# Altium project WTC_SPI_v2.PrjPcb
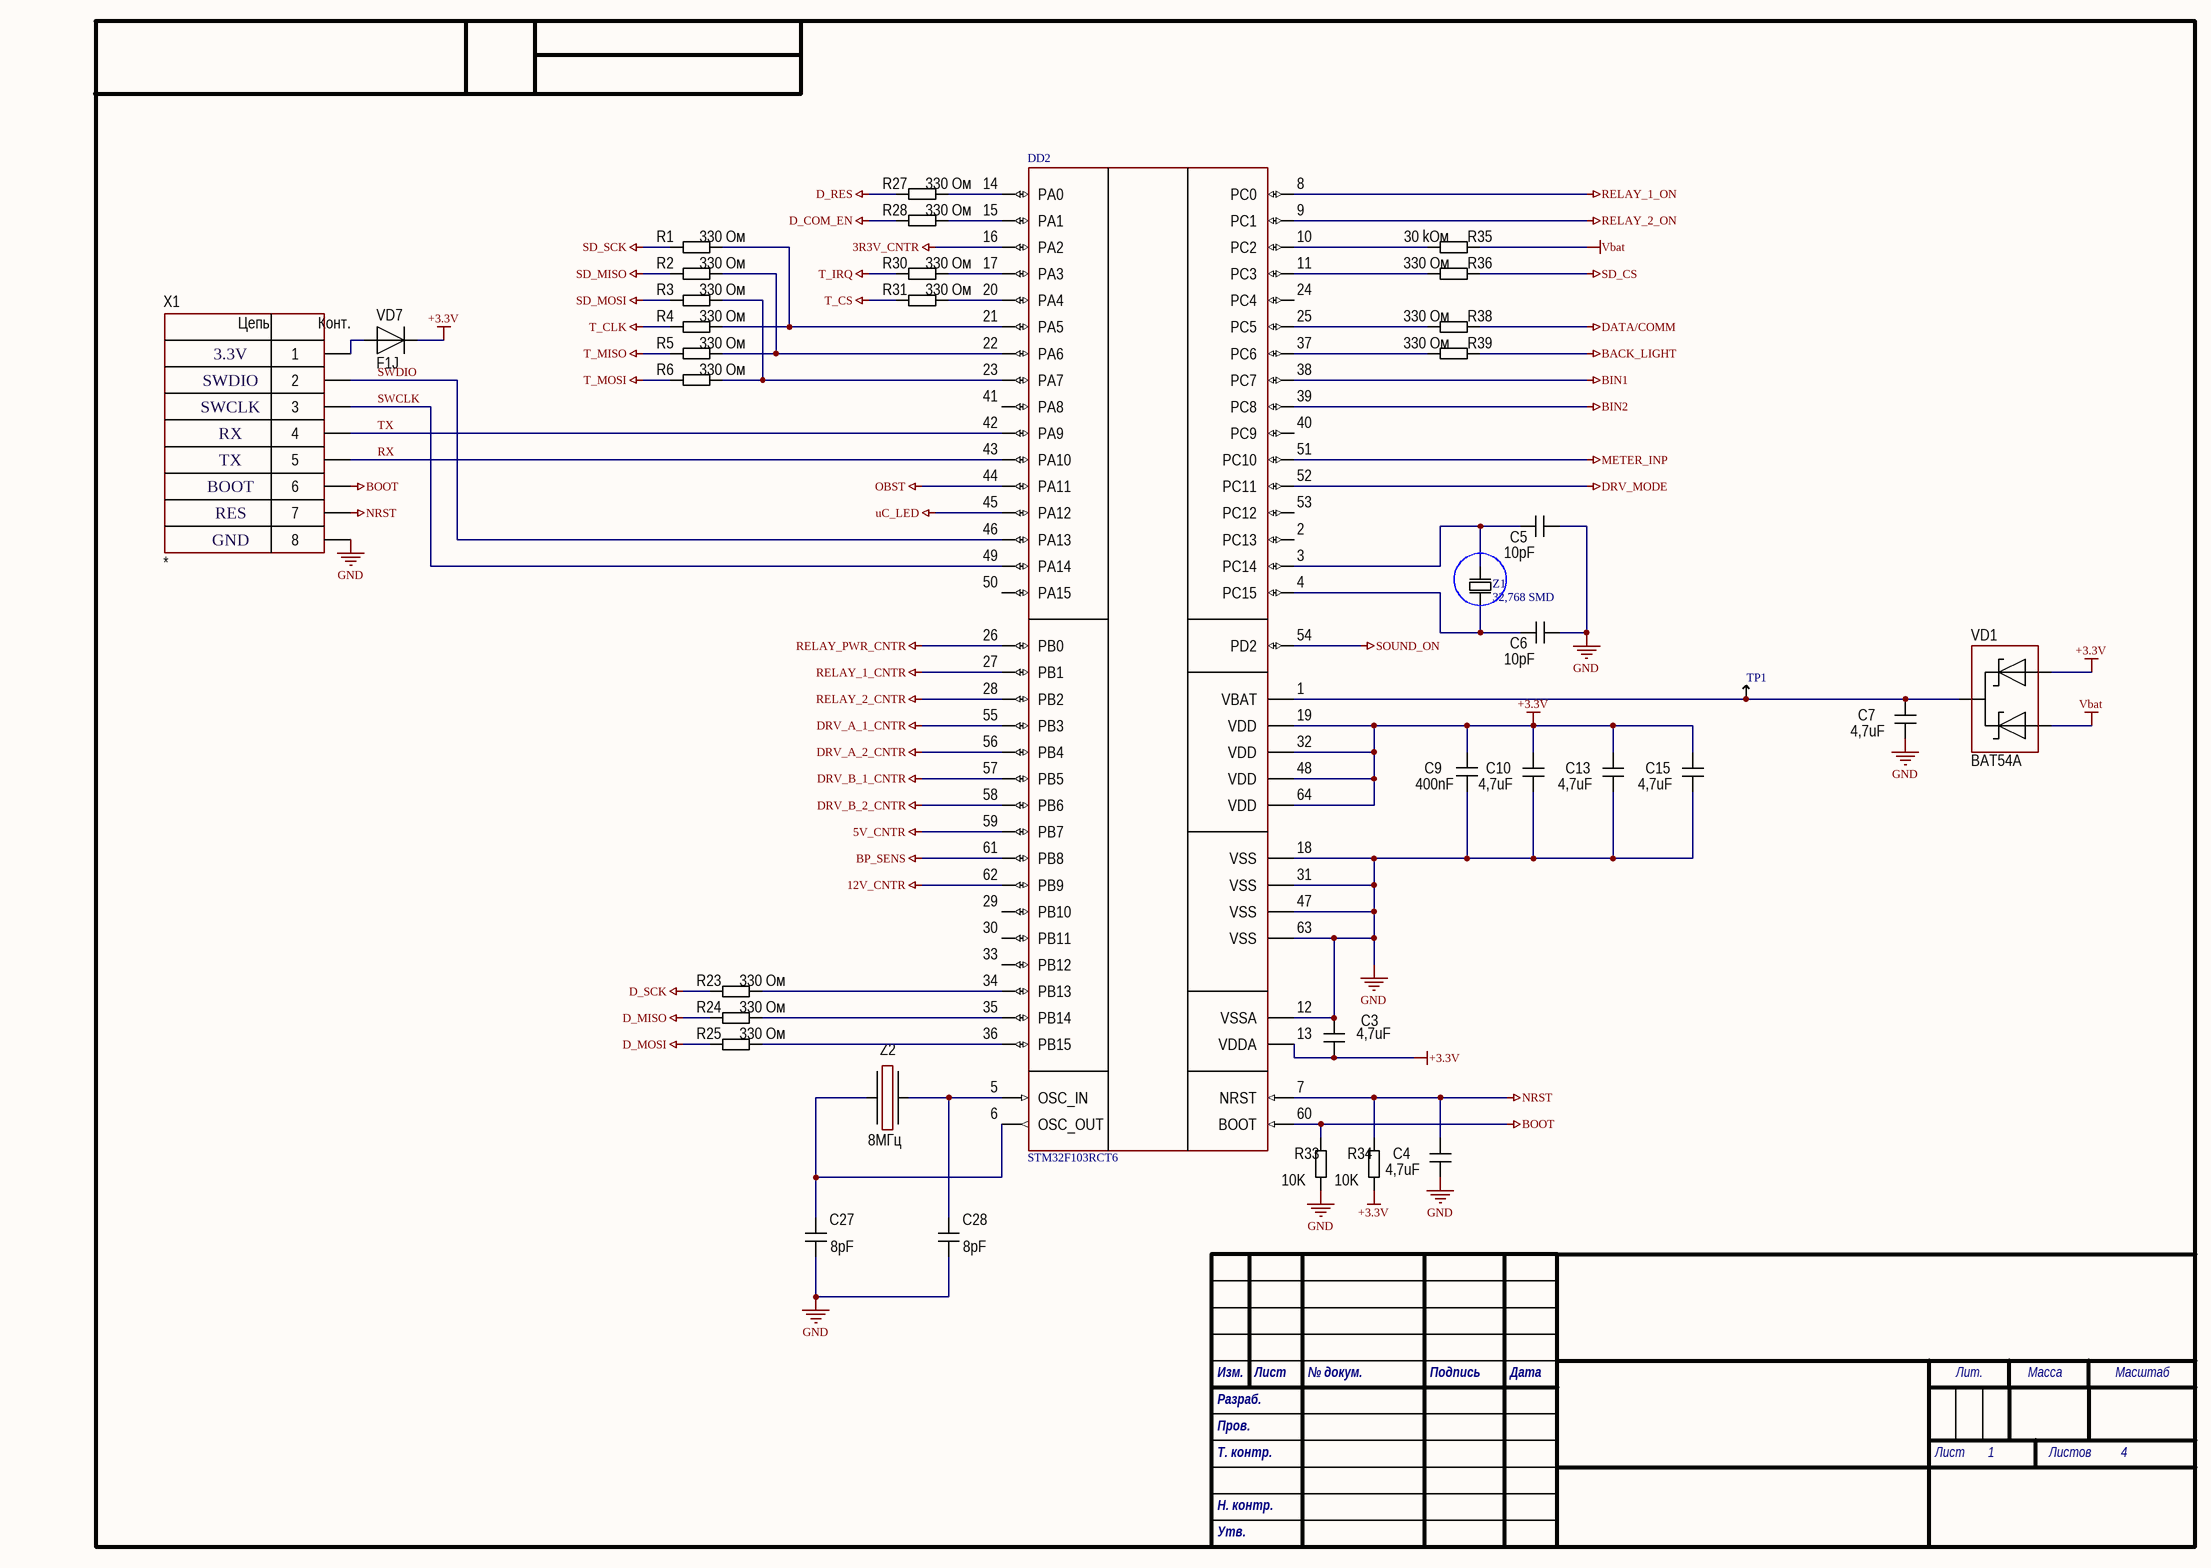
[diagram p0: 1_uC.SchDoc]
4 sheets, 165 parts. Net scope: global (net labels, ports and power ports of the same name join across sheets).
Sheets:
  1_uC.SchDoc
  2_PowerPerif.SchDoc
  3_InfoPerif.SchDoc
  4_PowerSupplie.SchDoc

## Sheet 1_uC.SchDoc
size 414 x 293 mm; SheetNumber: 1; SheetTotal: 4

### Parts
C3  4,7uF  [CH0402C]
C4  4,7uF  [CH0402C]
C5  10pF  [CH0402C]
C6  10pF  [CH0402C]
C7  4,7uF  [CH0402C]
C9  400nF  [CH0402C]
C10  4,7uF  [CH0402C]
C13  4,7uF  [CH0402C]
C15  4,7uF  [CH0402C]
C27  8pF  [CH0402C]
C28  8pF  [CH0402C]
DD2  STM32F103RCT6  [64-LQFP]
R1  330 Ом  [CH0603R]
R2  330 Ом  [CH0603R]
R3  330 Ом  [CH0603R]
R4  330 Ом  [CH0603R]
R5  330 Ом  [CH0603R]
R6  330 Ом  [CH0603R]
R23  330 Ом  [CH0603R]
R24  330 Ом  [CH0603R]
R25  330 Ом  [CH0603R]
R27  330 Ом  [CH0603R]
R28  330 Ом  [CH0603R]
R30  330 Ом  [CH0603R]
R31  330 Ом  [CH0603R]
R33  10K  [CH0805R]
R34  10K  [CH0805R]
R35  30 kОм  [CH0603R]
R36  330 Ом  [CH0603R]
R38  330 Ом  [CH0603R]
R39  330 Ом  [CH0603R]
TP1  TestPoint  (value not drawn)
VD1  BAT54A  [SOT23_123]
VD7  F1J  [SOD123F]
X1  *  [CON: PLS-8]
Z1  32,768 SMD  [SMD 32.768KHz]
Z2  8МГц  [OSC: ABM3]

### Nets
3R3V_CNTR: DD2.16(PA2)
5V_CNTR: DD2.59(PB7)
12V_CNTR: DD2.62(PB9)
+3.3V: C3.1 C9.1 C10.2 C13.2 C15.2 DD2.13(VDDA) DD2.19(VDD) DD2.32(VDD) DD2.48(VDD) DD2.64(VDD) R34.1 VD1.1 VD7.2
BACK_LIGHT: R39.1
BIN1: DD2.38(PC7)
BIN2: DD2.39(PC8)
BOOT: DD2.60(BOOT) R33.2 X1.6
BP_SENS: DD2.61(PB8)
D_COM_EN: R28.1
D_MISO: R24.1
D_MOSI: R25.1
D_RES: R27.1
D_SCK: R23.1
DATA/COMM: R38.1
DRV_A_1_CNTR: DD2.55(PB3)
DRV_A_2_CNTR: DD2.56(PB4)
DRV_B_1_CNTR: DD2.57(PB5)
DRV_B_2_CNTR: DD2.58(PB6)
DRV_MODE: DD2.52(PC11)
GND: C3.2 C4.1 C5.2 C6.1 C7.1 C9.2 C10.1 C13.1 C15.1 C27.1 C28.1 DD2.12(VSSA) DD2.18(VSS) DD2.31(VSS) DD2.47(VSS) DD2.63(VSS) R33.1 X1.8
METER_INP: DD2.51(PC10)
NRST: C4.2 DD2.7(NRST) R34.2 X1.7
OBST: DD2.44(PA11)
RELAY_1_CNTR: DD2.27(PB1)
RELAY_1_ON: DD2.8(PC0)
RELAY_2_CNTR: DD2.28(PB2)
RELAY_2_ON: DD2.9(PC1)
RELAY_PWR_CNTR: DD2.26(PB0)
RX: DD2.43(PA10) X1.5
SD_CS: R36.1
SD_MISO: R2.1
SD_MOSI: R3.1
SD_SCK: R1.1
SOUND_ON: DD2.54(PD2)
T_CLK: R4.1
T_CS: R31.1
T_IRQ: R30.1
T_MISO: R5.1
T_MOSI: R6.1
TX: DD2.42(PA9) X1.4
uC_LED: DD2.45(PA12)
Vbat: R35.1 VD1.3
SWCLK: DD2.49(PA14) X1.3
SWDIO: DD2.46(PA13) X1.2
NetC5_1: C5.1 DD2.3(PC14) Z1.1
NetC6_2: C6.2 DD2.4(PC15) Z1.2
NetC7_2: C7.2 DD2.1(VBAT) TP1.0 VD1.2
NetC27_2: C27.2 DD2.6(OSC_OUT) Z2.1
NetC28_2: C28.2 DD2.5(OSC_IN) Z2.3
NetDD2_10: DD2.10(PC2) R35.2
NetDD2_11: DD2.11(PC3) R36.2
NetDD2_14: DD2.14(PA0) R27.2
NetDD2_15: DD2.15(PA1) R28.2
NetDD2_17: DD2.17(PA3) R30.2
NetDD2_20: DD2.20(PA4) R31.2
NetDD2_21: DD2.21(PA5) R1.2 R4.2
NetDD2_22: DD2.22(PA6) R2.2 R5.2
NetDD2_23: DD2.23(PA7) R3.2 R6.2
NetDD2_25: DD2.25(PC5) R38.2
NetDD2_34: DD2.34(PB13) R23.2
NetDD2_35: DD2.35(PB14) R24.2
NetDD2_36: DD2.36(PB15) R25.2
NetDD2_37: DD2.37(PC6) R39.2
NetVD7_1: VD7.1 X1.1

Not connected (* = marked no-connect by the designer): DD2 2(PC13) 24(PC4) 29(PB10) 30(PB11) 33(PB12) 40(PC9) 41(PA8) 50(PA15) 53(PC12)

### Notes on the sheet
- 3.3V
- SWDIO
- SWCLK
- RX
- TX
- BOOT
- RES
- GND

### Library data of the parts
C3-C6 C9 C10 C13 C15 C27 C28 = Capacitor: 0402
C7 = Capacitor
DD2 = STM32F103RCT6: Cortex-M3 (64-LQFP)
R1-R6 R23-R25 R27 R28 R30 R31 R35 R36 R38 R39 = Resistor: 0603
R33 R34 = Resistor: 0805
VD1 = Diod Schottky Array v.1: SOT-23
VD7 = Diod
X1 = 8-Connector: Pin header 8
Z1 = Kvarc_32,768: 32,768 kHz SMD 8mm x 3.8mm 12,5pF
Z2 = Oscillator: NX5032GA-8MHz

## Sheet 2_PowerPerif.SchDoc
size 414 x 293 mm; SheetNumber: 2; SheetTotal: 4
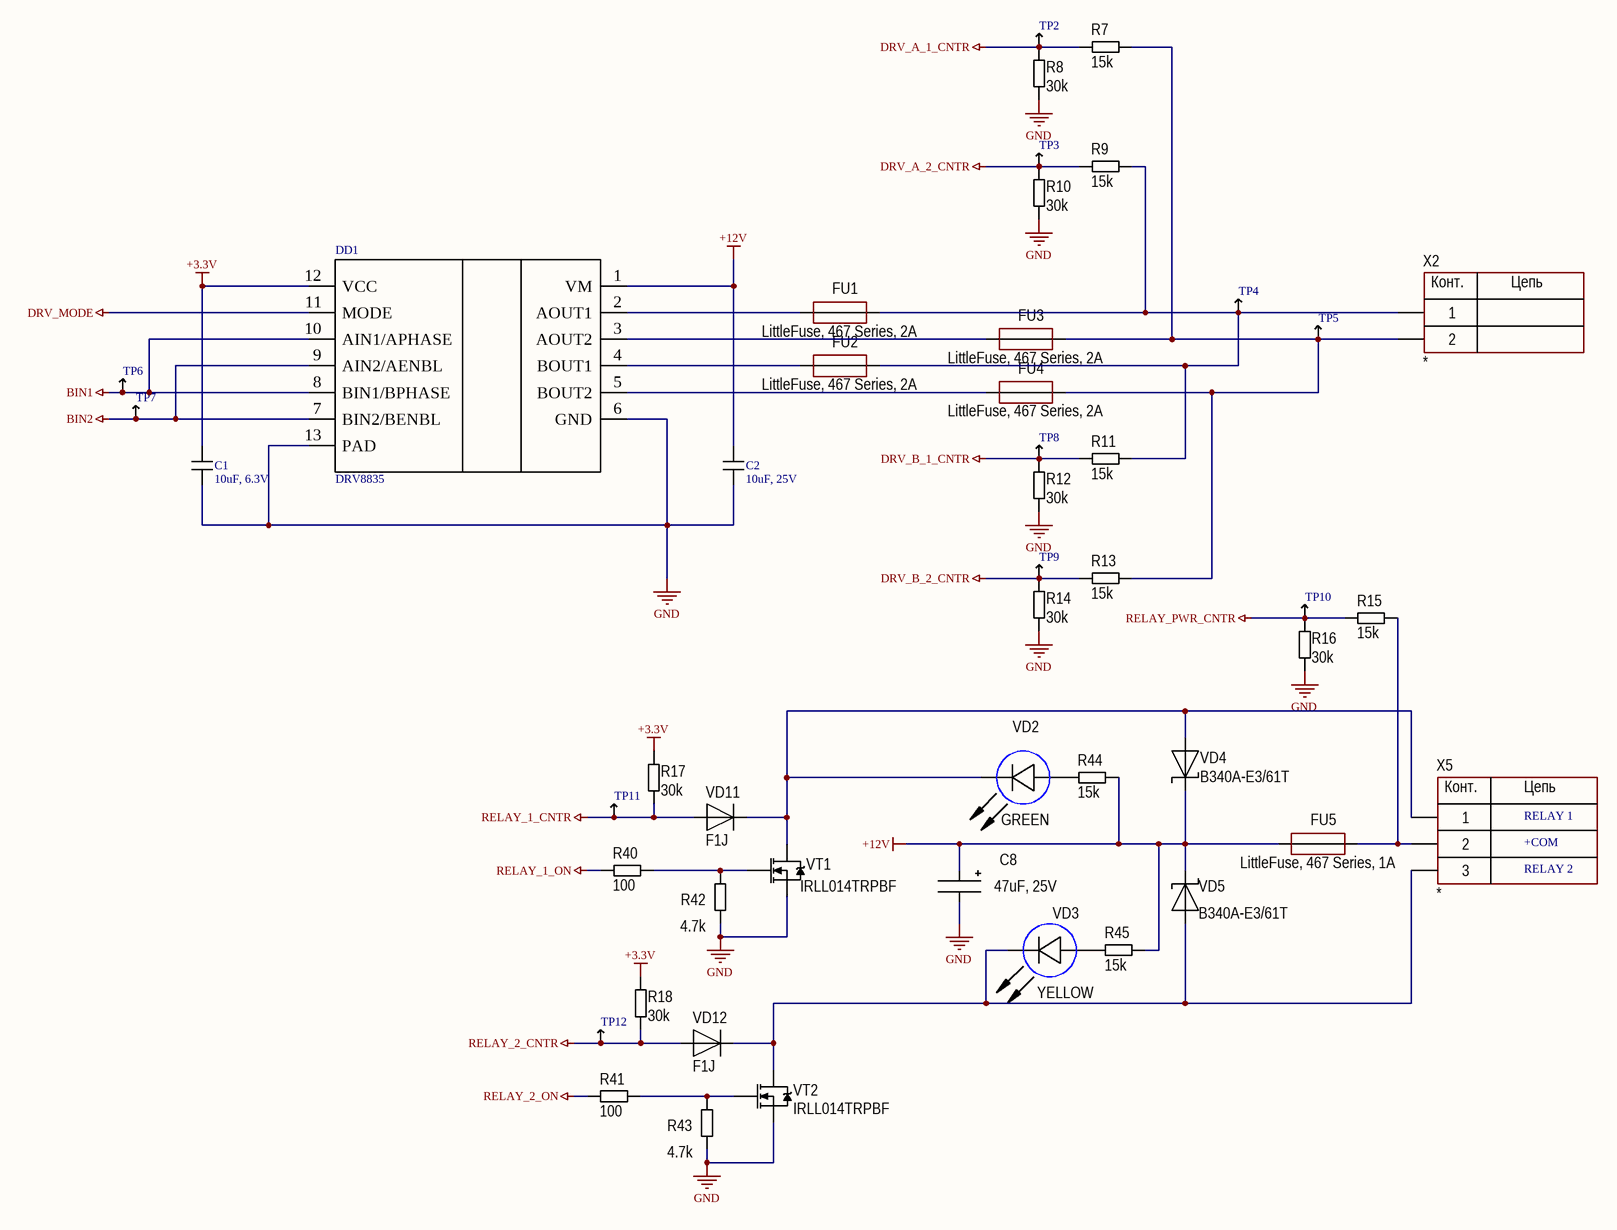
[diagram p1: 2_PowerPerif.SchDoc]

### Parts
C1  10uF, 6.3V  [C_0603]
C2  10uF, 25V  [C_0603]
C8  47uF, 25V  [D8C3.2H12]
DD1  DRV8835  [WSON12]
FU1  LittleFuse, 467 Series, 2A  [CH0603F]
FU2  LittleFuse, 467 Series, 2A  [CH0603F]
FU3  LittleFuse, 467 Series, 2A  [CH0603F]
FU4  LittleFuse, 467 Series, 2A  [CH0603F]
FU5  LittleFuse, 467 Series, 1A  [CH0603F]
R7  15k  [CH0805R]
R8  30k  [CH0805R]
R9  15k  [CH0805R]
R10  30k  [CH0805R]
R11  15k  [CH0805R]
R12  30k  [CH0805R]
R13  15k  [CH0805R]
R14  30k  [CH0805R]
R15  15k  [CH0805R]
R16  30k  [CH0805R]
R17  30k  [CH0805R]
R18  30k  [CH0805R]
R40  100  [CH0805R]
R41  100  [CH0805R]
R42  4.7k  [CH0805R]
R43  4.7k  [CH0805R]
R44  15k  [CH0805R]
R45  15k  [CH0805R]
TP2  TestPoint  (value not drawn)
TP3  TestPoint  (value not drawn)
TP4  TestPoint  (value not drawn)
TP5  TestPoint  (value not drawn)
TP6  TestPoint  (value not drawn)
TP7  TestPoint  (value not drawn)
TP8  TestPoint  (value not drawn)
TP9  TestPoint  (value not drawn)
TP10  TestPoint  (value not drawn)
TP11  TestPoint  (value not drawn)
TP12  TestPoint  (value not drawn)
VD2  GREEN  [CH0603LB]
VD3  YELLOW  [CH0603LB]
VD4  B340A-E3/61T  [SMA]
VD5  B340A-E3/61T  [SMA]
VD11  F1J  [SOD123F]
VD12  F1J  [SOD123F]
VT1  IRLL014TRPBF  [SOT223]
VT2  IRLL014TRPBF  [SOT223]
X2  *  [CON: CWF-2]
X5  *  [CON: 300-03P-5.0]

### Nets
+3.3V: C1.2 DD1.12(VCC) R17.2 R18.2
+12V: C2.2 C8.1 DD1.1(VM) FU5.1 R44.2 R45.2 VD4.2 VD5.2
BIN1: DD1.8(BIN1/BPHASE) DD1.10(AIN1/APHASE) TP6.0
BIN2: DD1.7(BIN2/BENBL) DD1.9(AIN2/AENBL) TP7.0
DRV_A_1_CNTR: R7.1 R8.2 TP2.0
DRV_A_2_CNTR: R9.1 R10.2 TP3.0
DRV_B_1_CNTR: R11.1 R12.2 TP8.0
DRV_B_2_CNTR: R13.1 R14.2 TP9.0
DRV_MODE: DD1.11(MODE)
GND: C1.1 C2.1 C8.2 DD1.6(GND) DD1.13(PAD) R8.1 R10.1 R12.1 R14.1 R16.1 R42.1 R43.1 VT1.3(S) VT2.3(S)
RELAY_1_CNTR: R17.1 TP11.0 VD11.1
RELAY_1_ON: R40.2
RELAY_2_CNTR: R18.1 TP12.0 VD12.1
RELAY_2_ON: R41.2
RELAY_PWR_CNTR: R15.1 R16.2 TP10.0
NetDD1_2: DD1.2(AOUT1) FU1.1
NetDD1_3: DD1.3(AOUT2) FU3.1
NetDD1_4: DD1.4(BOUT1) FU2.1
NetDD1_5: DD1.5(BOUT2) FU4.1
NetFU1_2: FU1.2 FU2.2 R9.2 R11.2 TP4.0 X2.1
NetFU3_2: FU3.2 FU4.2 R7.2 R13.2 TP5.0 X2.2
NetFU5_2: FU5.2 R15.2 X5.2
NetR40_1: R40.1 R42.2 VT1.1(G)
NetR41_1: R41.1 R43.2 VT2.1(G)
NetR44_1: R44.1 VD2.1(A)
NetR45_1: R45.1 VD3.1(A)
NetVD2_2: VD2.2(C) VD4.1 VD11.2 VT1.2(D) X5.1
NetVD3_2: VD3.2(C) VD5.1 VD12.2 VT2.2(D) X5.3

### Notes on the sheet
- RELAY 1
- +COM
- RELAY 2

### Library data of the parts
C1 C2 = C_SMD
C8 = AlumCap
DD1 = DRV8835: Driver
FU1-FU5 = Fuse
R7-R18 R40-R45 = Resistor
VD2 VD3 = LED_1
VD4 VD5 = Diod Schottky
VD11 VD12 = Diod
VT1 VT2 = N-chanel: Mosfet
X2 = 2-Connector
X5 = 3-Connector

## Sheet 3_InfoPerif.SchDoc
size 414 x 293 mm; SheetNumber: 3; SheetTotal: 4
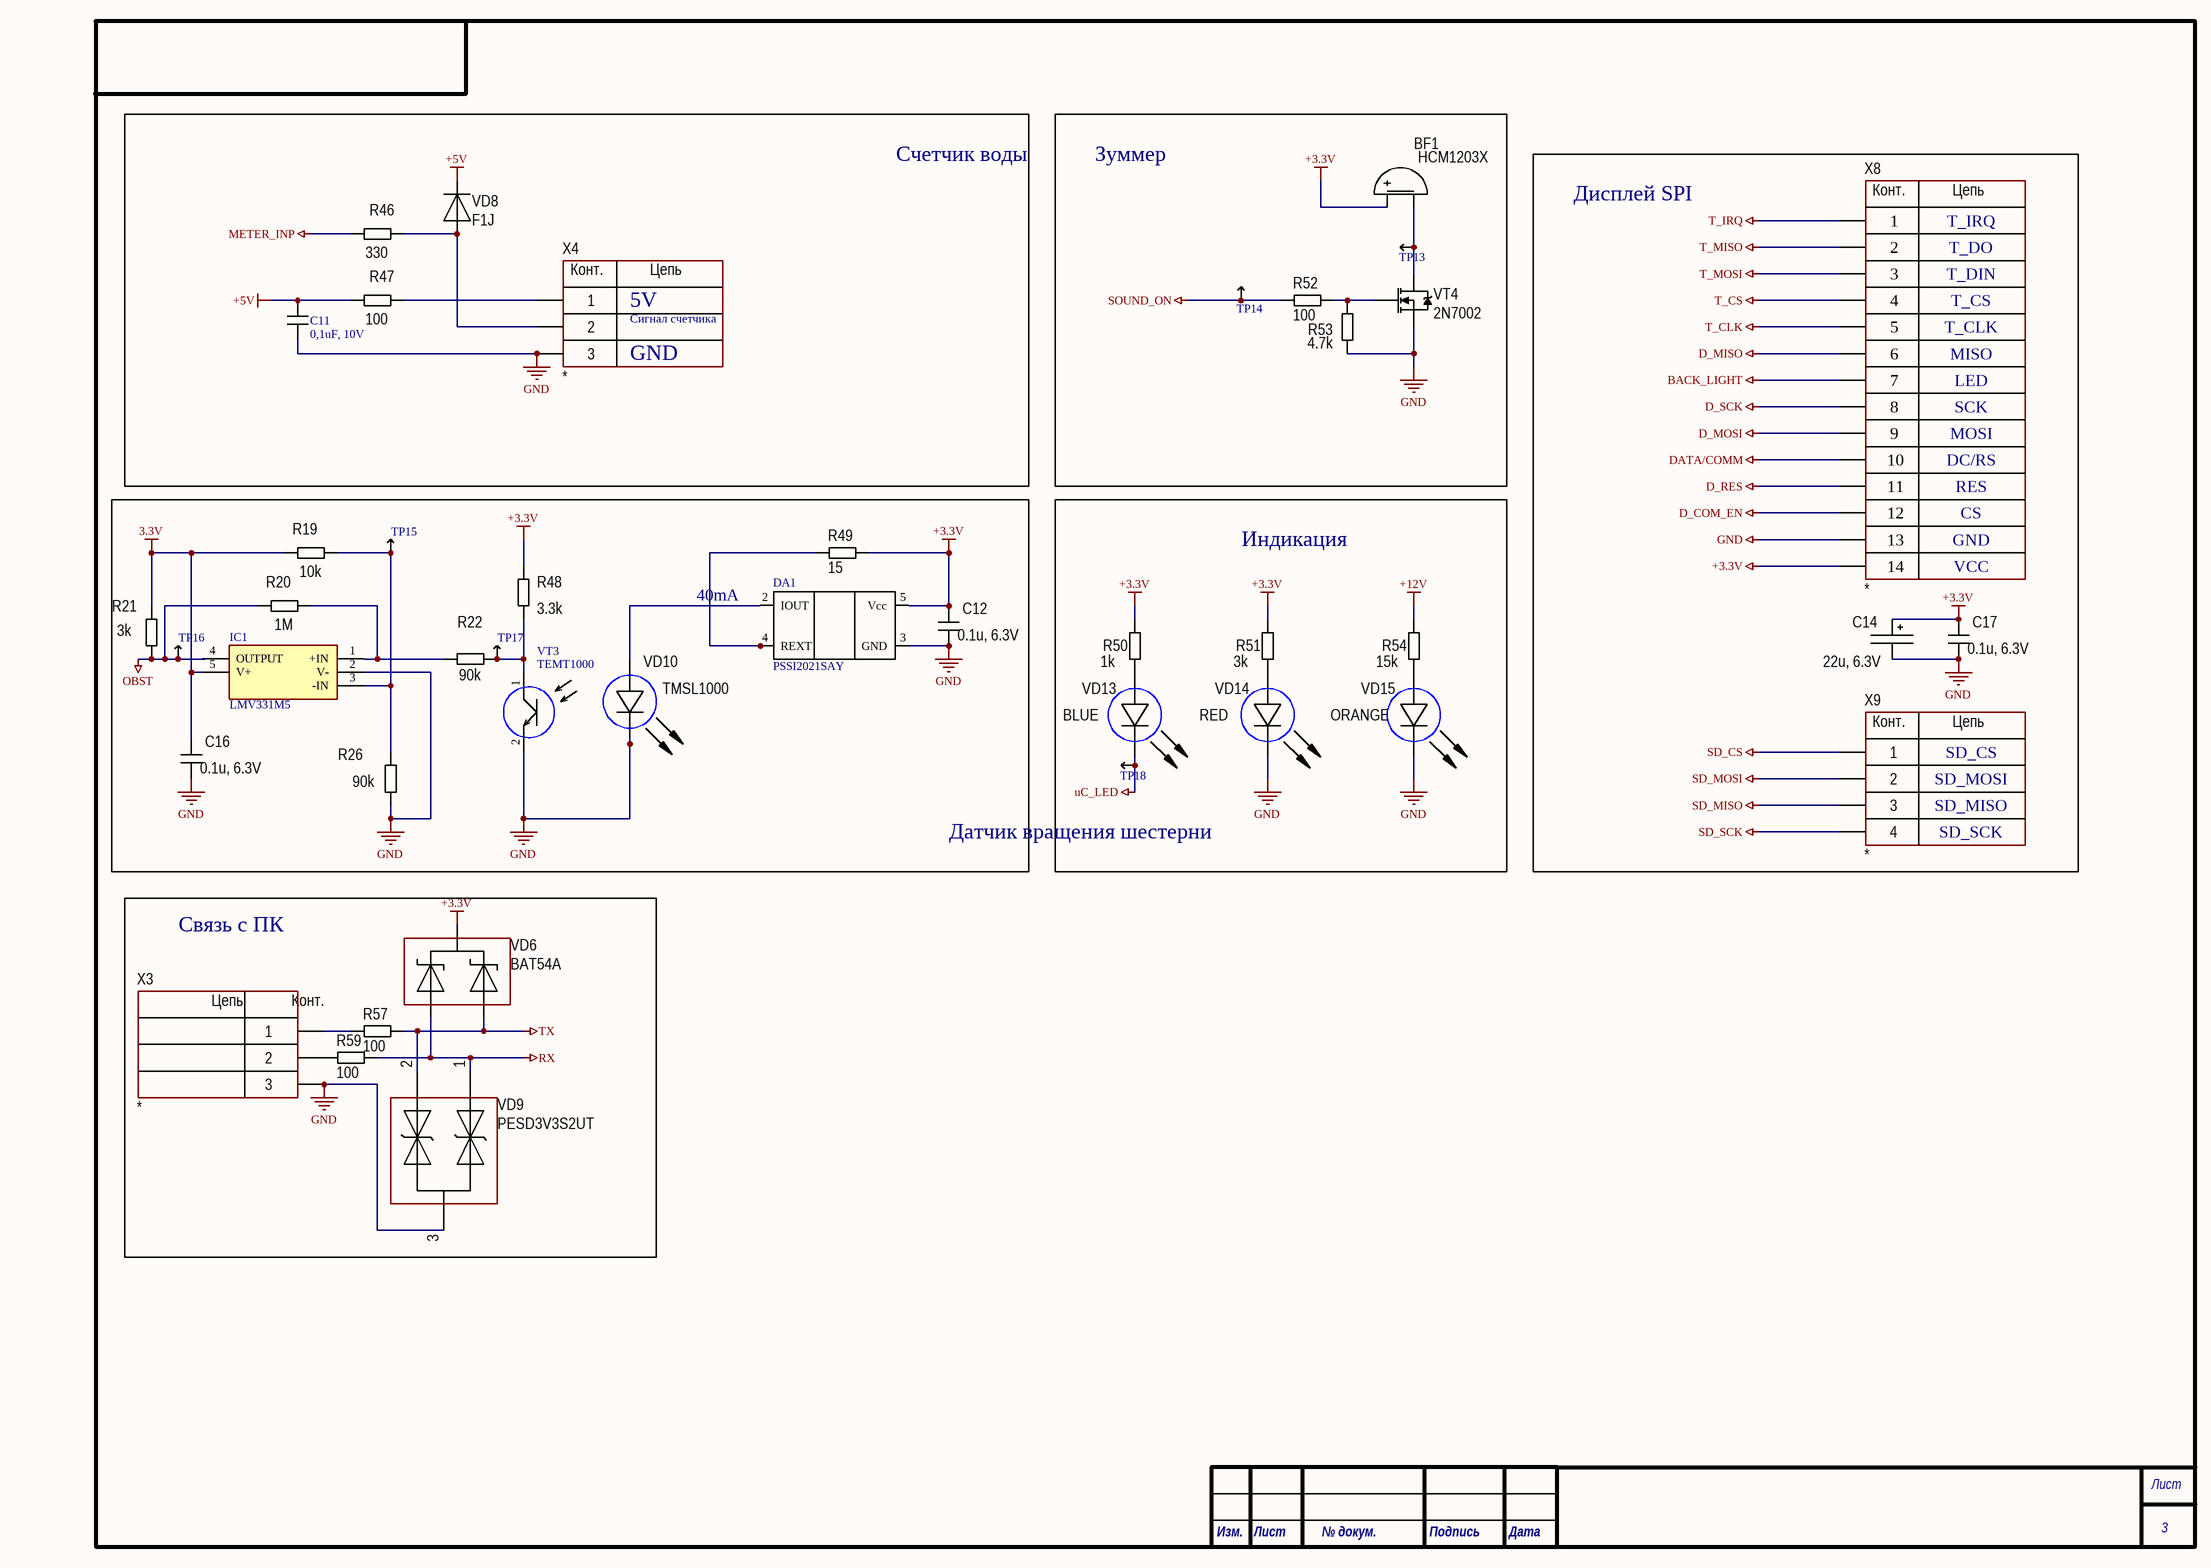
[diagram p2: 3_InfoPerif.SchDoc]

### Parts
BF1  HCM1203X  [BUZ: AI-1223-TWT-3V-2-R]
C11  0,1uF, 10V  [C_0603]
C12  0.1u, 6.3V  [CH0805C]
C14  22u, 6.3V  [TANTAL_B]
C16  0.1u, 6.3V  [CH0805C]
C17  0.1u, 6.3V  [CH0805C]
DA1  PSSI2021SAY  [SOT353]
IC1  LMV331M5  [SOT95P280X145-5N]
R19  10k  [CH0805R]
R20  1M  [CH0805R]
R21  3k  [CH0805R]
R22  90k  [CH0805R]
R26  90k  [CH0805R]
R46  330  [CH0805R]
R47  100  [CH2512R]
R48  3.3k  [CH0805R]
R49  15  [CH0805R]
R50  1k  [CH0805R]
R51  3k  [CH0805R]
R52  100  [CH0805R]
R53  4.7k  [CH0805R]
R54  15k  [CH0805R]
R57  100  [CH0805R]
R59  100  [CH0805R]
TP13  TestPoint  (value not drawn)
TP14  TestPoint  (value not drawn)
TP15  TestPoint  (value not drawn)
TP16  TestPoint  (value not drawn)
TP17  TestPoint  (value not drawn)
TP18  TestPoint  (value not drawn)
VD6  BAT54A  [SOT23_123]
VD8  F1J  [SOD123F]
VD9  PESD3V3S2UT  [SOT23_132]
VD10  TMSL1000  [TSML1000]
VD13  BLUE  [CH0603LB]
VD14  RED  [CH0603LB]
VD15  ORANGE  [CH0603LB]
VT3  TEMT1000  [TEMT1000]
VT4  2N7002  [SOT23_123]
X3  *  [CON: CWF-3]
X4  *  [CON: CWF-3]
X8  *  [DS1024-14]
X9  *  [DS1023-4]

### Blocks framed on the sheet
Зуммер: BF1 R52 R53 TP13 TP14 VT4
Дисплей SPI: C14 C17 X8 X9
Датчик вращения шестерни: C12 C16 DA1 IC1 R19-R22 R26 R48 R49 TP15-TP17 VD10 VT3
Индикация: R50 R51 R54 TP18 VD13-VD15
Связь с ПК: R57 R59 VD6 VD9 X3

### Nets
3.3V: C16.2 IC1.5(V+) R19.2 R21.2
+3.3V: BF1.1(+) C12.2 C14.1 C17.2 R48.2 R49.2 R50.2 R51.2 VD6.2 X8.14
+5V: C11.2 R47.1 VD8.2
+12V: R54.2
BACK_LIGHT: X8.7
D_COM_EN: X8.12
D_MISO: X8.6
D_MOSI: X8.9
D_RES: X8.11
D_SCK: X8.8
DATA/COMM: X8.10
GND: C11.1 C12.1 C14.2 C16.1 C17.1 DA1.3(GND) IC1.2(V-) R26.1 R53.1 VD9.3 VD10.2(C) VD14.2(C) VD15.2(C) VT3.2 VT4.3(S) X3.3 X4.3 X8.13
METER_INP: R46.1
OBST: IC1.4(OUTPUT) R20.2 R21.1 TP16.0
RX: R59.2 VD6.3 VD9.1
SD_CS: X9.1
SD_MISO: X9.3
SD_MOSI: X9.2
SD_SCK: X9.4
SOUND_ON: R52.2 TP14.0
T_CLK: X8.5
T_CS: X8.4
T_IRQ: X8.1
T_MISO: X8.2
T_MOSI: X8.3
TX: R57.2 VD6.1 VD9.2
uC_LED: TP18.0 VD13.2(C)
NetBF1_2: BF1.2(-) TP13.0 VT4.2(D)
NetDA1_2: DA1.2(IOUT) VD10.1(A)
NetDA1_4: DA1.4(REXT) R49.1
NetIC1_1: IC1.1(+IN) R20.1 R22.2
NetIC1_3: IC1.3(-IN) R19.1 R26.2 TP15.0
NetR22_1: R22.1 R48.1 TP17.0 VT3.1
NetR46_2: R46.2 VD8.1 X4.2
NetR47_2: R47.2 X4.1
NetR50_1: R50.1 VD13.1(A)
NetR51_1: R51.1 VD14.1(A)
NetR52_1: R52.1 R53.2 VT4.1(G)
NetR54_1: R54.1 VD15.1(A)
NetR57_1: R57.1 X3.1
NetR59_1: R59.1 X3.2

Not connected (* = marked no-connect by the designer): DA1 5(Vcc)

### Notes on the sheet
- Счетчик воды
- T_IRQ
- 5V
- T_DO
- T_DIN
- T_CS
- GND
- Сигнал счетчика
- T_CLK
- MISO
- LED
- SCK
- MOSI
- DC/RS
- RES
- CS
- VCC
- 40mA
- SD_CS
- SD_MOSI
- SD_MISO
- SD_SCK

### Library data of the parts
BF1 = Buzzer: Manufacturer: PUI Audio, Inc.; Model: AI-1223-TWT-3V-2-R
C11 = C_SMD
C12 C16 = Capacitor: 0805
C14 = TantalCap
C17 = Capacitor
DA1 = PSSI2021SAY: Iout = 0.617/Rext + 15 µA
IC1 = LMV331M5: Integrated Circuit; Manufacturer_Name: Texas Instruments
R19-R22 R26 R46 R47 R50-R54 R57 R59 = Resistor
R48 R49 = Resistor: 0805
VD6 = Diod Schottky Array v.1
VD8 = Diod
VD9 = TVS Array
VD10 VD13-VD15 = LED_1
VT4 = N-chanel: Mosfet
X3 X4 = 3-Connector
X8 = 14-Connector
X9 = 4-Connector

## Sheet 4_PowerSupplie.SchDoc
size 414 x 293 mm; SheetNumber: 4; SheetTotal: 4; PageSetup: Record=PageOptionsZCenterHorizontal=TrueZCenterVertical=TrueZPrintScale=1.00ZXCorrection=0.00ZYCorrection=0.00ZPrintKind=1ZBorderSize=5000000ZLeftOffset=0ZBottomOffset=0ZOrientation=2ZPaperLength=1000ZPaperWidth=1000ZScale=100ZPaperSource=7ZPrintQuality=-4ZMediaType=1ZDitherType=10ZPaperKind=A3ZPrintScaleMode=0; Razrabotal: {Разработал}; Proveril: {Проверил}; Tkontr: {Т.контр.}; Nkontr: {Н.контр.}; Ytverdil: {Утвердил}; Nazvanie1: {Название1}; Nazvanie2: {Название2}; Oboznachenie: {Обозначение}
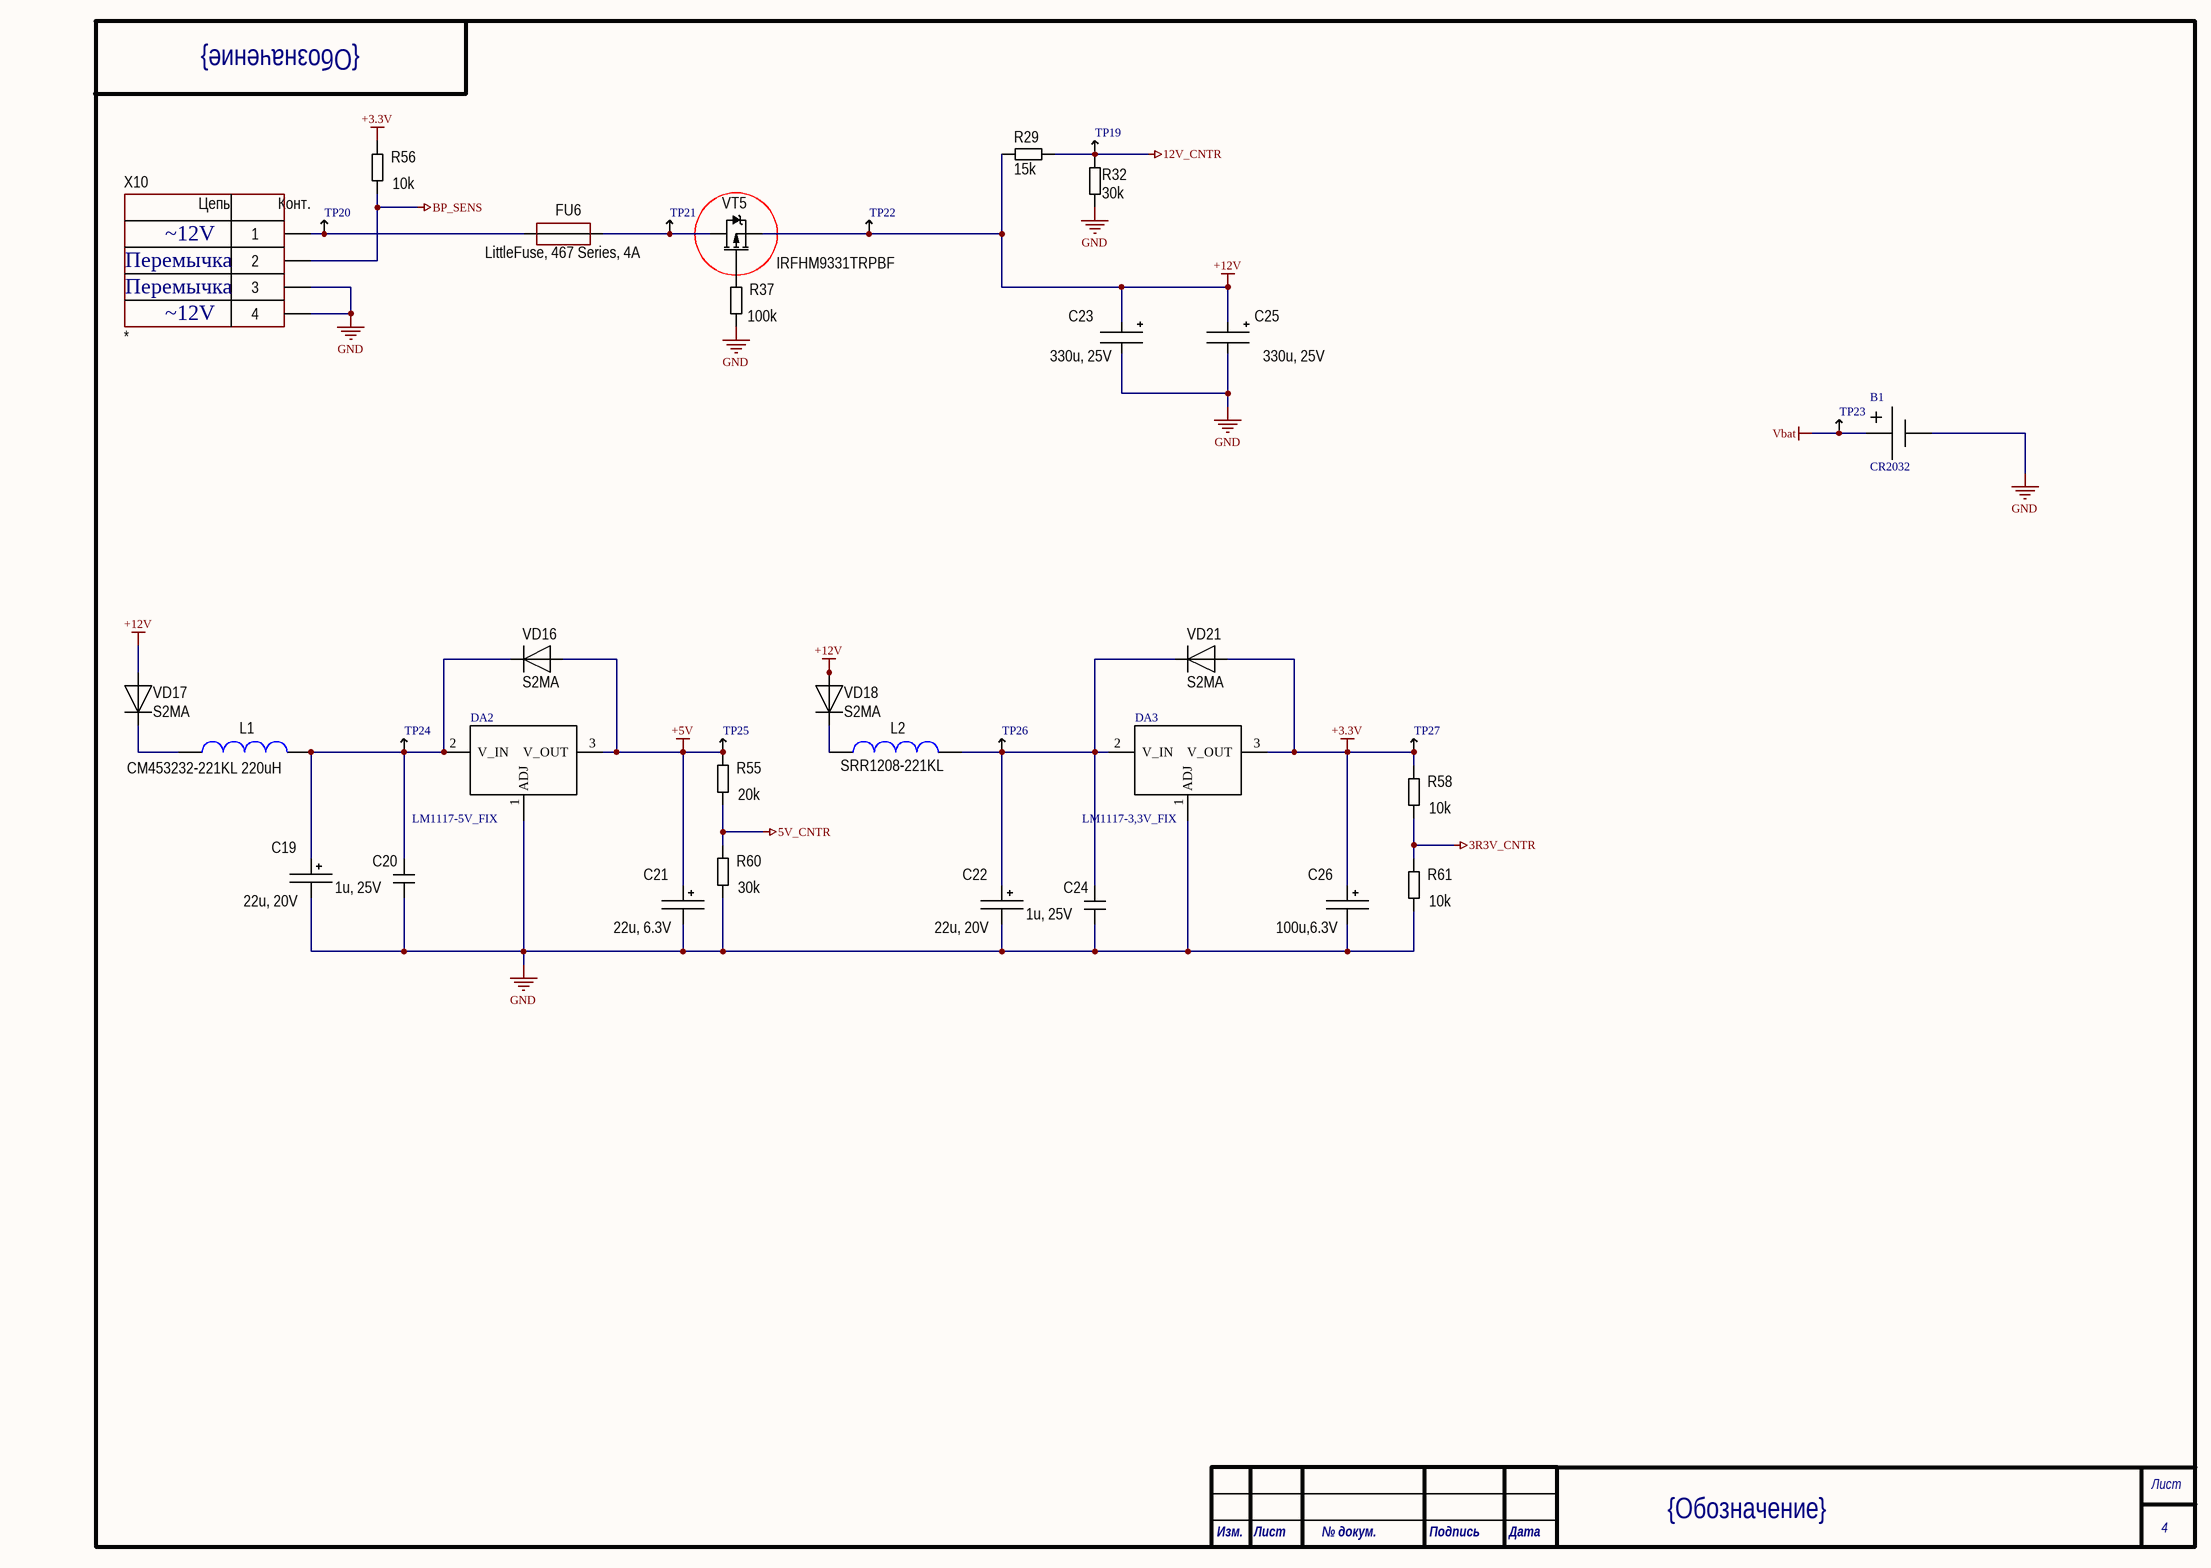
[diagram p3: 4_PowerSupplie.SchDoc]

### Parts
B1  CR2032  [CR2032]
C19  22u, 20V  [TANTAL_B]
C20  1u, 25V  [CH0805C]
C21  22u, 6.3V  [TANTAL_B]
C22  22u, 20V  [TANTAL_B]
C23  330u, 25V  [D10C4.4H10]
C24  1u, 25V  [CH0805C]
C25  330u, 25V  [D10C4.4H10]
C26  100u,6.3V  [TANTAL_B]
DA2  LM1117-5V_FIX  [SOT223_123]
DA3  LM1117-3,3V_FIX  [SOT223_123]
FU6  LittleFuse, 467 Series, 4A  [CH0603F]
L1  CM453232-221KL 220uH  [IND:1812]
L2  SRR1208-221KL  [IND: SRR1208]
R29  15k  [CH0805R]
R32  30k  [CH0805R]
R37  100k  [CH0805R]
R55  20k  [CH0805R]
R56  10k  [CH0805R]
R58  10k  [CH0805R]
R60  30k  [CH0805R]
R61  10k  [CH0805R]
TP19  TestPoint  (value not drawn)
TP20  TestPoint  (value not drawn)
TP21  TestPoint  (value not drawn)
TP22  TestPoint  (value not drawn)
TP23  TestPoint  (value not drawn)
TP24  TestPoint  (value not drawn)
TP25  TestPoint  (value not drawn)
TP26  TestPoint  (value not drawn)
TP27  TestPoint  (value not drawn)
VD16  S2MA  [SMA]
VD17  S2MA  [SMA]
VD18  S2MA  [SMA]
VD21  S2MA  [SMA]
VT5  IRFHM9331TRPBF  [SOT223]
X10  *  [CON: CWF-4]

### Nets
3R3V_CNTR: R58.1 R61.2
5V_CNTR: R55.1 R60.2
12V_CNTR: R29.1 R32.2 TP19.0
+3.3V: C26.1 DA3.3(V_OUT) R56.2 R58.2 TP27.0 VD21.1
+5V: C21.1 DA2.3(V_OUT) R55.2 TP25.0 VD16.1
+12V: C23.1 C25.1 R29.2 TP22.0 VD17.1 VD18.1 VT5.3(S)
BP_SENS: R56.1 X10.2
GND: B1.2 C19.2 C20.1 C21.2 C22.2 C23.2 C24.1 C25.2 C26.2 DA2.1(ADJ) DA3.1(ADJ) R32.1 R37.1 R60.1 R61.1 X10.3 X10.4
Vbat: B1.1 TP23.0
NetC19_1: C19.1 C20.2 DA2.2(V_IN) L1.1 TP24.0 VD16.2
NetC22_1: C22.1 C24.2 DA3.2(V_IN) L2.1 TP26.0 VD21.2
NetFU6_1: FU6.1 TP20.0 X10.1
NetFU6_2: FU6.2 TP21.0 VT5.2(D)
NetL1_2: L1.2 VD17.2
NetL2_2: L2.2 VD18.2
NetR37_2: R37.2 VT5.1(G)

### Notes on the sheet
- Перемычка
- 2V

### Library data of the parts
B1 = Battery_CR2032
C19 C21 C22 C26 = TantalCap
C20 C24 = Capacitor
C23 C25 = AlumCap
DA2 DA3 = LM1117
FU6 = Fuse
L1 L2 = Inductor
R29 R32 R37 R55 R56 R58 R60 R61 = Resistor
VD16-VD18 VD21 = Diod
VT5 = P-chanel: Mosfet
X10 = 4-Connector

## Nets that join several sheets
3R3V_CNTR: 1_uC (DD2.16), 4_PowerSupplie (R58.1 R61.2)
5V_CNTR: 1_uC (DD2.59), 4_PowerSupplie (R55.1 R60.2)
12V_CNTR: 1_uC (DD2.62), 4_PowerSupplie (R29.1 R32.2 TP19.0)
+3.3V: 1_uC (13 pins), 2_PowerPerif (C1.2 DD1.12 R17.2 R18.2), 3_InfoPerif (10 pins), 4_PowerSupplie (6 pins)
+5V: 3_InfoPerif (C11.2 R47.1 VD8.2), 4_PowerSupplie (5 pins)
+12V: 2_PowerPerif (8 pins), 3_InfoPerif (R54.2), 4_PowerSupplie (7 pins)
BACK_LIGHT: 1_uC (R39.1), 3_InfoPerif (X8.7)
BIN1: 1_uC (DD2.38), 2_PowerPerif (DD1.8 DD1.10 TP6.0)
BIN2: 1_uC (DD2.39), 2_PowerPerif (DD1.7 DD1.9 TP7.0)
BP_SENS: 1_uC (DD2.61), 4_PowerSupplie (R56.1 X10.2)
D_COM_EN: 1_uC (R28.1), 3_InfoPerif (X8.12)
D_MISO: 1_uC (R24.1), 3_InfoPerif (X8.6)
D_MOSI: 1_uC (R25.1), 3_InfoPerif (X8.9)
D_RES: 1_uC (R27.1), 3_InfoPerif (X8.11)
D_SCK: 1_uC (R23.1), 3_InfoPerif (X8.8)
DATA/COMM: 1_uC (R38.1), 3_InfoPerif (X8.10)
DRV_A_1_CNTR: 1_uC (DD2.55), 2_PowerPerif (R7.1 R8.2 TP2.0)
DRV_A_2_CNTR: 1_uC (DD2.56), 2_PowerPerif (R9.1 R10.2 TP3.0)
DRV_B_1_CNTR: 1_uC (DD2.57), 2_PowerPerif (R11.1 R12.2 TP8.0)
DRV_B_2_CNTR: 1_uC (DD2.58), 2_PowerPerif (R13.1 R14.2 TP9.0)
DRV_MODE: 1_uC (DD2.52), 2_PowerPerif (DD1.11)
GND: 1_uC (18 pins), 2_PowerPerif (14 pins), 3_InfoPerif (18 pins), 4_PowerSupplie (17 pins)
METER_INP: 1_uC (DD2.51), 3_InfoPerif (R46.1)
OBST: 1_uC (DD2.44), 3_InfoPerif (IC1.4 R20.2 R21.1 TP16.0)
RELAY_1_CNTR: 1_uC (DD2.27), 2_PowerPerif (R17.1 TP11.0 VD11.1)
RELAY_1_ON: 1_uC (DD2.8), 2_PowerPerif (R40.2)
RELAY_2_CNTR: 1_uC (DD2.28), 2_PowerPerif (R18.1 TP12.0 VD12.1)
RELAY_2_ON: 1_uC (DD2.9), 2_PowerPerif (R41.2)
RELAY_PWR_CNTR: 1_uC (DD2.26), 2_PowerPerif (R15.1 R16.2 TP10.0)
RX: 1_uC (DD2.43 X1.5), 3_InfoPerif (R59.2 VD6.3 VD9.1)
SD_CS: 1_uC (R36.1), 3_InfoPerif (X9.1)
SD_MISO: 1_uC (R2.1), 3_InfoPerif (X9.3)
SD_MOSI: 1_uC (R3.1), 3_InfoPerif (X9.2)
SD_SCK: 1_uC (R1.1), 3_InfoPerif (X9.4)
SOUND_ON: 1_uC (DD2.54), 3_InfoPerif (R52.2 TP14.0)
T_CLK: 1_uC (R4.1), 3_InfoPerif (X8.5)
T_CS: 1_uC (R31.1), 3_InfoPerif (X8.4)
T_IRQ: 1_uC (R30.1), 3_InfoPerif (X8.1)
T_MISO: 1_uC (R5.1), 3_InfoPerif (X8.2)
T_MOSI: 1_uC (R6.1), 3_InfoPerif (X8.3)
TX: 1_uC (DD2.42 X1.4), 3_InfoPerif (R57.2 VD6.1 VD9.2)
uC_LED: 1_uC (DD2.45), 3_InfoPerif (TP18.0 VD13.2)
Vbat: 1_uC (R35.1 VD1.3), 4_PowerSupplie (B1.1 TP23.0)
